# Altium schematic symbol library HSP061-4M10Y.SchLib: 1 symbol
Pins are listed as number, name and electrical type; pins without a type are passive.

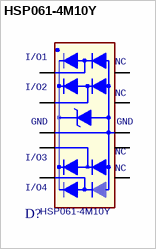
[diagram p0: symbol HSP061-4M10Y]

## HSP061-4M10Y
designator D?
footprint ST_QFN50P260X110X50-10L
pins: 1 I/O1, 2 I/O2, 3 GND, 4 I/O3, 5 I/O4, 6 NC1, 7 NC2, 8 GND1, 9 NC3, 10 NC4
